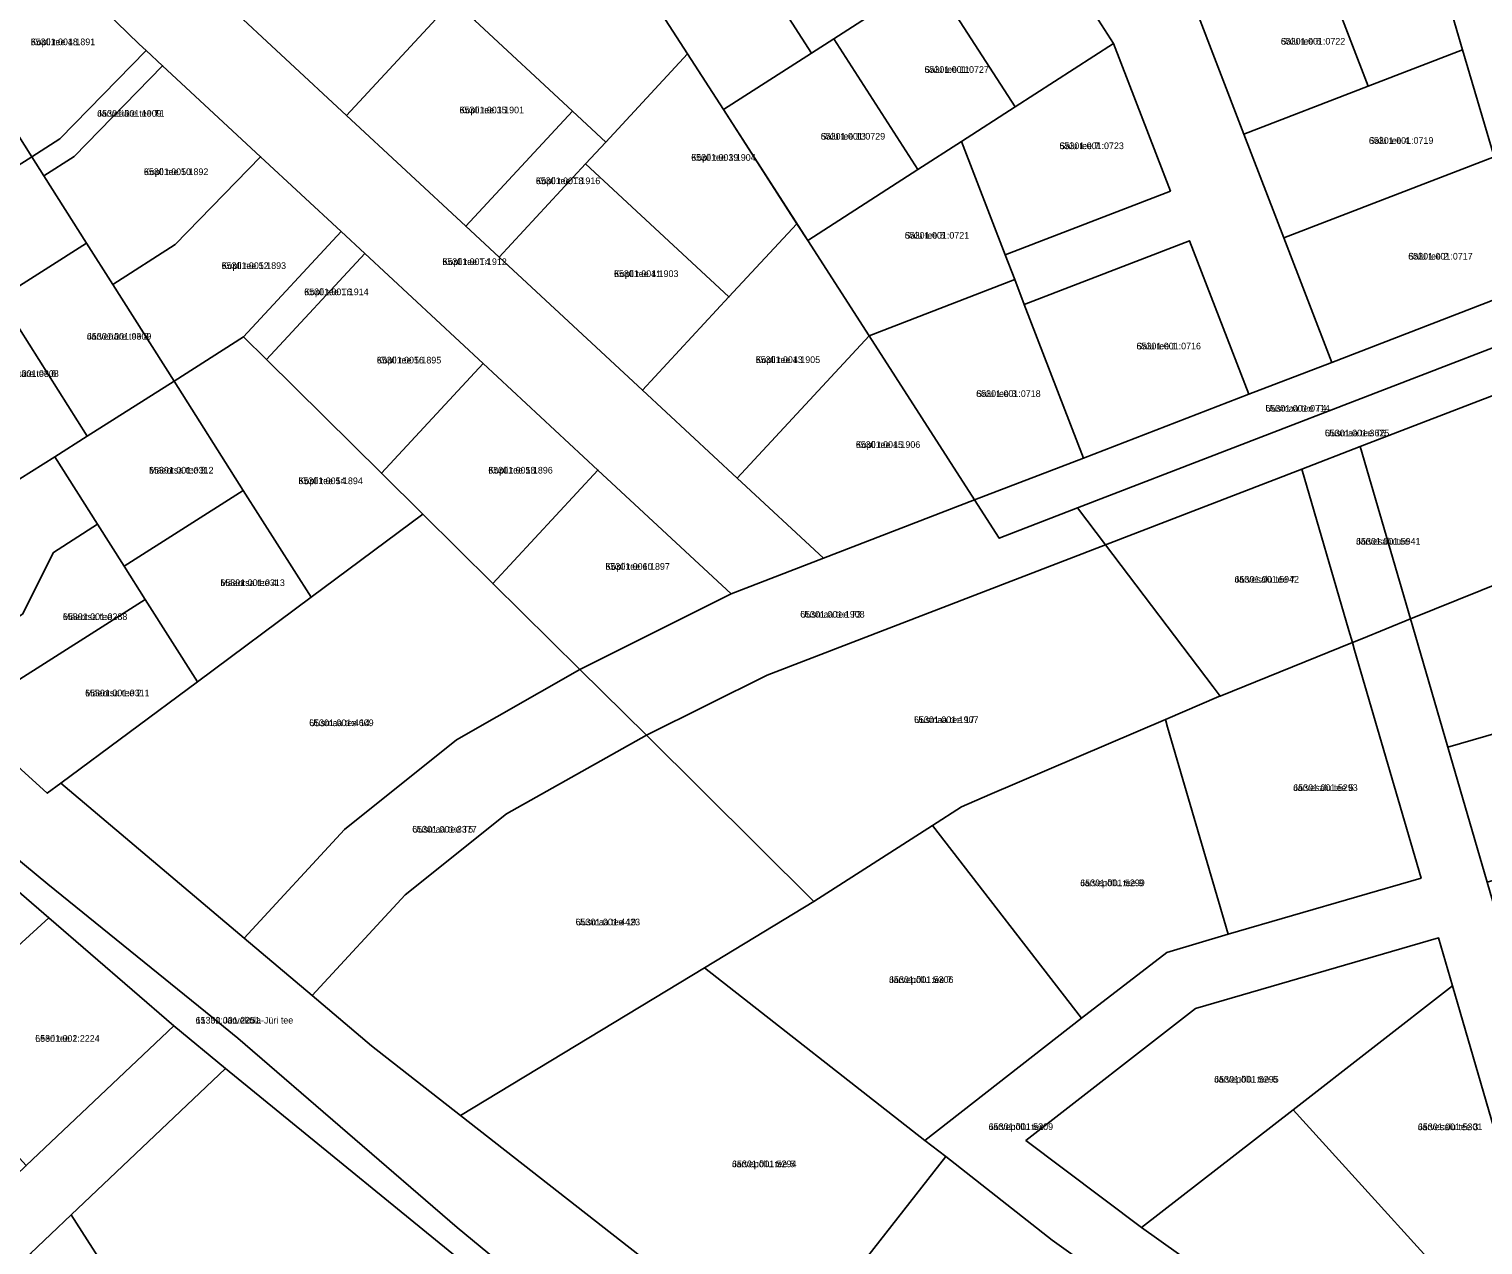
# Model space of a CAD drawing. Extents: x 543236 to 563717, y 6566033 to 6588992.
# Drawn here: x 545303.2 to 545630.4, y 6584014.2 to 6584287.7 of the extents above; entities that cross this region are included whole.
import ezdxf

# ---------------------------------------------------------------- set-up
doc = ezdxf.new("R2010")
doc.units = 0
for name, color, linetype in [('L_AADRESS', 7, 'Continuous'), ('PIIR', 7, 'Continuous'), ('TUNNUS', 7, 'Continuous')]:
    doc.layers.add(name, color=color, linetype=linetype)

msp = doc.modelspace()

# ---------------------------------------------------------------- linework, layer by layer
at = {"layer": 'PIIR'}
for points in [[(545612.18, 6584329.34), (545667.39, 6584358.85), (545675.07, 6584344.48), (545698.18, 6584306.68), (545692.06, 6584302.94), (545696.57, 6584295.46), (545702.81, 6584299.16), (545716.82, 6584276.21), (545641.37, 6584230.07), (545632.88, 6584258.94), (545625.8, 6584283.01), (545615.16, 6584319.21)], [(545591.04, 6584309.91), (545615.16, 6584319.21), (545625.8, 6584283.01), (545604.56, 6584274.83), (545593.2, 6584304.32)], [(545347.2, 6584293.73), (545365.08, 6584312.07), (545374.36, 6584316.68), (545398.67, 6584294.12), (545374.65, 6584268.24)], [(545403.55, 6584289.59), (545428.95, 6584316.96), (545437.53, 6584303.64), (545451.4, 6584282.08), (545432.99, 6584262.25), (545425.51, 6584269.2)], [(545437.53, 6584303.64), (545457.33, 6584316.38), (545472.78, 6584292.38), (545479.27, 6584282.29), (545459.47, 6584269.55)], [(545506.15, 6584299.59), (545528.32, 6584313.86), (545547.27, 6584284.42), (545525.09, 6584270.15)], [(545277.65, 6584300.25), (545305.02, 6584309.24), (545309.36, 6584302.45), (545312.61, 6584299.31), (545328.02, 6584284.27), (545329.53, 6584282.87), (545310.17, 6584263.01), (545303.83, 6584258.96), (545293.5, 6584275.25), (545288.57, 6584283.02), (545283.65, 6584290.79)], [(545312.61, 6584299.31), (545316.44, 6584301.26), (545319.44, 6584302.75), (545331.19, 6584308.57), (545347.2, 6584293.73), (545374.65, 6584268.24), (545401.49, 6584243.33), (545408.98, 6584236.38), (545441.22, 6584206.45), (545462.52, 6584186.68), (545481.97, 6584168.63), (545461.22, 6584160.63), (545431.23, 6584188.46), (545405.41, 6584212.43), (545378.77, 6584237.16), (545373.41, 6584242.13), (545355.3, 6584258.94), (545333.24, 6584279.42), (545329.53, 6584282.87), (545328.02, 6584284.27)], [(545565.2, 6584293.52), (545593.2, 6584304.32), (545604.56, 6584274.83), (545576.56, 6584264.03)], [(545484.28, 6584285.51), (545506.15, 6584299.59), (545525.09, 6584270.15), (545513.03, 6584262.38), (545503.23, 6584256.08)], [(545374.65, 6584268.24), (545398.67, 6584294.12), (545403.55, 6584289.59), (545425.51, 6584269.2), (545401.49, 6584243.33)], [(545459.47, 6584269.55), (545479.27, 6584282.29), (545484.28, 6584285.51), (545503.23, 6584256.08), (545478.42, 6584240.11)], [(545303.83, 6584258.96), (545310.17, 6584263.01), (545329.53, 6584282.87), (545333.24, 6584279.42), (545313.33, 6584258.99), (545306.55, 6584254.66)], [(545513.03, 6584262.38), (545525.09, 6584270.15), (545547.27, 6584284.42), (545560.05, 6584251.25), (545522.84, 6584236.91)], [(545576.56, 6584264.03), (545604.56, 6584274.83), (545625.8, 6584283.01), (545632.88, 6584258.94), (545585.55, 6584240.71)], [(545306.55, 6584254.66), (545313.33, 6584258.99), (545333.24, 6584279.42), (545355.3, 6584258.94), (545336.06, 6584239.22), (545322.04, 6584230.24), (545316.15, 6584239.53)], [(545428.44, 6584257.35), (545432.99, 6584262.25), (545451.4, 6584282.08), (545459.47, 6584269.55), (545475.98, 6584243.89), (545460.68, 6584227.42)], [(545293.5, 6584275.25), (545303.83, 6584258.96), (545275.29, 6584240.86), (545264.95, 6584257.15)], [(545401.49, 6584243.33), (545425.51, 6584269.2), (545432.99, 6584262.25), (545428.44, 6584257.35), (545408.98, 6584236.38)], [(545478.42, 6584240.11), (545503.23, 6584256.08), (545513.03, 6584262.38), (545522.84, 6584236.91), (545525, 6584231.31), (545492.22, 6584218.68)], [(545303.83, 6584258.96), (545306.55, 6584254.66), (545316.15, 6584239.53), (545296.61, 6584227.14), (545292.25, 6584234.03), (545274.49, 6584222.77), (545256.48, 6584211.35), (545230.26, 6584185.73), (545221.37, 6584193.81), (545226.59, 6584198.99), (545222.37, 6584203.25), (545216.92, 6584197.85), (545205.45, 6584208.27), (545215.52, 6584219.38), (545232.18, 6584204.25), (545244.15, 6584216), (545251.22, 6584222.04), (545258.99, 6584226.97), (545271.83, 6584235.11), (545276.89, 6584238.32), (545275.29, 6584240.86)], [(545322.04, 6584230.24), (545336.06, 6584239.22), (545355.3, 6584258.94), (545373.41, 6584242.13), (545351.46, 6584218.48), (545335.83, 6584208.5)], [(545408.98, 6584236.38), (545428.44, 6584257.35), (545460.68, 6584227.42), (545441.22, 6584206.45)], [(545585.55, 6584240.71), (545632.88, 6584258.94), (545641.37, 6584230.07), (545596.34, 6584212.71)], [(545441.22, 6584206.45), (545460.68, 6584227.42), (545475.98, 6584243.89), (545478.42, 6584240.11), (545492.22, 6584218.68), (545462.52, 6584186.68)], [(545351.46, 6584218.48), (545373.41, 6584242.13), (545378.77, 6584237.16), (545356.66, 6584213.33)], [(545527.16, 6584225.71), (545564.37, 6584240.05), (545577.67, 6584205.52), (545540.46, 6584191.18)], [(545316.15, 6584239.53), (545322.04, 6584230.24), (545335.83, 6584208.5), (545316.29, 6584196.11), (545296.61, 6584227.14)], [(545356.66, 6584213.33), (545378.77, 6584237.16), (545405.41, 6584212.43), (545382.51, 6584187.76)], [(545292.25, 6584234.03), (545296.61, 6584227.14), (545316.29, 6584196.11), (545309, 6584191.48), (545298.54, 6584184.85), (545274.49, 6584222.77)], [(545492.22, 6584218.68), (545525, 6584231.31), (545527.16, 6584225.71), (545540.46, 6584191.18), (545515.98, 6584181.75)], [(545515.98, 6584181.75), (545540.46, 6584191.18), (545577.67, 6584205.52), (545596.34, 6584212.71), (545641.37, 6584230.07), (545644.2, 6584220.44), (545539.13, 6584179.98), (545521.51, 6584173.16)], [(545589.61, 6584188.69), (545545.44, 6584171.67), (545539.13, 6584179.98), (545644.2, 6584220.44), (545647.04, 6584210.83), (545602.73, 6584193.75)], [(545335.83, 6584208.5), (545351.46, 6584218.48), (545356.66, 6584213.33), (545382.51, 6584187.76), (545391.8, 6584178.56), (545366.66, 6584159.89), (545351.42, 6584183.91)], [(545462.52, 6584186.68), (545492.22, 6584218.68), (545515.98, 6584181.75), (545481.97, 6584168.63)], [(545382.51, 6584187.76), (545405.41, 6584212.43), (545431.23, 6584188.46), (545407.54, 6584162.96), (545391.8, 6584178.56)], [(545614.04, 6584154.98), (545602.73, 6584193.75), (545647.04, 6584210.83), (545658.68, 6584171.22), (545645.72, 6584167.8)], [(545335.83, 6584208.5), (545351.42, 6584183.91), (545324.59, 6584166.89), (545318.64, 6584176.28), (545309, 6584191.48), (545316.29, 6584196.11)], [(545309, 6584191.48), (545318.64, 6584176.28), (545308.69, 6584169.97), (545301.71, 6584156.08), (545278.87, 6584141.59), (545258.91, 6584159.72), (545280.53, 6584173.43), (545298.54, 6584184.85)], [(545600.19, 6584152.36), (545589.61, 6584188.69), (545602.73, 6584193.75), (545614.04, 6584154.98), (545603.14, 6584150.55), (545600.98, 6584149.67)], [(545407.54, 6584162.96), (545431.23, 6584188.46), (545461.22, 6584160.63), (545427.18, 6584143.62)], [(545569.65, 6584139.73), (545545.44, 6584171.67), (545589.61, 6584188.69), (545600.19, 6584152.36), (545600.98, 6584149.67), (545571.22, 6584137.62)], [(545351.42, 6584183.91), (545366.66, 6584159.89), (545341.1, 6584140.87), (545329.35, 6584159.39), (545324.59, 6584166.89)], [(545427.18, 6584143.62), (545461.22, 6584160.63), (545481.97, 6584168.63), (545515.98, 6584181.75), (545521.51, 6584173.16), (545539.13, 6584179.98), (545545.44, 6584171.67), (545469.29, 6584142.31), (545442.16, 6584128.83)], [(545366.66, 6584159.89), (545391.8, 6584178.56), (545407.54, 6584162.96), (545427.18, 6584143.62), (545399.42, 6584127.78), (545374.18, 6584107.66), (545351.64, 6584083.21), (545310.33, 6584118.05), (545341.1, 6584140.87)], [(545212.59, 6584169.83), (545213.47, 6584170.7), (545217.62, 6584174.69), (545257.23, 6584138.18), (545270.35, 6584126.61), (545286.81, 6584112.39), (545307.45, 6584095.3), (545342.89, 6584066.65), (545350.19, 6584060.71), (545399.54, 6584018.08), (545436.69, 6583987.47), (545474.84, 6583958.99), (545470.74, 6583953.26), (545409.72, 6584003.02), (545347.4, 6584053.85), (545335.77, 6584063.49), (545307.68, 6584087.74), (545277.94, 6584113.41), (545243, 6584143.58)], [(545318.64, 6584176.28), (545324.59, 6584166.89), (545329.35, 6584159.39), (545288.08, 6584133.22), (545278.87, 6584141.59), (545301.71, 6584156.08), (545308.69, 6584169.97)], [(545442.16, 6584128.83), (545469.29, 6584142.31), (545545.44, 6584171.67), (545569.65, 6584139.73), (545571.22, 6584137.62), (545570.95, 6584137.51), (545558.9, 6584132.37), (545519.38, 6584115.5), (545513.01, 6584112.71), (545506.49, 6584108.5), (545479.83, 6584091.47)], [(545614.56, 6584153.2), (545614.04, 6584154.98), (545645.72, 6584167.8), (545658.68, 6584171.22), (545668.08, 6584139.32), (545622.46, 6584126.14)], [(545329.35, 6584159.39), (545341.1, 6584140.87), (545310.33, 6584118.05), (545307.29, 6584115.78), (545288.08, 6584133.22)], [(545559.4, 6584130.62), (545558.9, 6584132.37), (545570.95, 6584137.51), (545571.22, 6584137.62), (545600.98, 6584149.67), (545601.48, 6584147.97), (545616.45, 6584096.72), (545573.02, 6584084.05)], [(545366.92, 6584070.26), (545351.64, 6584083.21), (545374.18, 6584107.66), (545399.42, 6584127.78), (545427.18, 6584143.62), (545442.16, 6584128.83), (545410.67, 6584111.17), (545387.84, 6584092.97)], [(545631.3, 6584095.78), (545622.46, 6584126.14), (545668.08, 6584139.32), (545670.43, 6584131.35), (545676.89, 6584109)], [(545540.06, 6584065.17), (545506.49, 6584108.5), (545513.01, 6584112.71), (545519.38, 6584115.5), (545558.9, 6584132.37), (545559.4, 6584130.62), (545573.02, 6584084.05), (545559.24, 6584080)], [(545387.84, 6584092.97), (545410.67, 6584111.17), (545442.16, 6584128.83), (545479.83, 6584091.47), (545455.17, 6584076.54), (545400.3, 6584043.32), (545380.24, 6584059), (545366.92, 6584070.26)], [(545277.16, 6584059.95), (545250.9, 6584088.79), (545277.94, 6584113.41), (545307.68, 6584087.74)], [(545504.75, 6584037.71), (545455.17, 6584076.54), (545479.83, 6584091.47), (545506.49, 6584108.5), (545540.06, 6584065.17)], [(545277.16, 6584059.95), (545307.68, 6584087.74), (545335.77, 6584063.49), (545302.59, 6584032.02)], [(545553.55, 6584018.14), (545527.54, 6584037.71), (545565.7, 6584067.34), (545620.37, 6584083.26), (545623.49, 6584072.43), (545587.63, 6584044.56)], [(545472.49, 6583986.81), (545400.3, 6584043.32), (545455.17, 6584076.54), (545504.75, 6584037.71), (545509.47, 6584034.05)], [(545633.92, 6583993.55), (545587.63, 6584044.56), (545623.49, 6584072.43), (545643.82, 6584002.66)], [(545184.39, 6583922.14), (545187.41, 6583925.03), (545202.59, 6583938.1), (545222.62, 6583956.17), (545250.92, 6583983.02), (545260.06, 6583991.69), (545293.45, 6584023.35), (545302.59, 6584032.02), (545335.77, 6584063.49), (545347.4, 6584053.85), (545312.69, 6584020.93), (545303.56, 6584012.25), (545263.51, 6583974.28), (545254.34, 6583965.59), (545226.41, 6583939.39), (545217.05, 6583930.95), (545186.41, 6583903.29), (545183.3, 6583905.86), (545191.99, 6583913.79)], [(545312.69, 6584020.93), (545347.4, 6584053.85), (545409.72, 6584003.02), (545381.28, 6583963.21), (545322.94, 6584004.89)], [(545608.94, 6583978.69), (545553.55, 6584018.14), (545587.63, 6584044.56), (545633.92, 6583993.55), (545612.76, 6583974.48)], [(545497.57, 6583967.21), (545472.49, 6583986.81), (545509.47, 6584034.05), (545533.47, 6584015.24), (545572.68, 6583987.32), (545537.86, 6583938.49)], [(545307.09, 6583923.8), (545266.41, 6583952.86), (545254.34, 6583965.59), (545263.51, 6583974.28), (545274.79, 6583962.43), (545275.28, 6583962.08), (545307.39, 6583939.01), (545356.24, 6583904.18), (545380.64, 6583938.37), (545371.66, 6583954.62), (545340.53, 6583976.87), (545336.5, 6583979.74), (545314.08, 6583995.73), (545310.09, 6584002.03), (545303.56, 6584012.25), (545312.69, 6584020.93), (545322.94, 6584004.89), (545381.28, 6583963.21), (545395.56, 6583937.53), (545359.17, 6583886.59)]]:
    msp.add_lwpolyline(points, close=True, dxfattribs=at)
for points in [[(545565.2, 6584293.52), (545576.56, 6584264.03), (545585.55, 6584240.71), (545596.34, 6584212.71), (545577.67, 6584205.52), (545564.37, 6584240.05), (545527.16, 6584225.71), (545525, 6584231.31), (545522.84, 6584236.91), (545560.05, 6584251.25), (545547.27, 6584284.42), (545528.32, 6584313.86)], [(545506.15, 6584299.59), (545484.28, 6584285.51), (545479.27, 6584282.29), (545472.78, 6584292.38)], [(545436.69, 6583987.47), (545399.54, 6584018.08), (545350.19, 6584060.71), (545342.89, 6584066.65), (545307.45, 6584095.3), (545286.81, 6584112.39), (545270.35, 6584126.61), (545257.23, 6584138.18), (545217.62, 6584174.69), (545213.47, 6584170.7), (545212.86, 6584179.01), (545226.88, 6584188.8), (545258.91, 6584159.72), (545278.87, 6584141.59), (545288.08, 6584133.22), (545307.29, 6584115.78), (545310.33, 6584118.05), (545351.64, 6584083.21), (545366.92, 6584070.26), (545380.24, 6584059), (545400.3, 6584043.32), (545472.49, 6583986.81)], [(545572.68, 6583987.32), (545533.47, 6584015.24), (545509.47, 6584034.05), (545504.75, 6584037.71), (545540.06, 6584065.17), (545559.24, 6584080), (545573.02, 6584084.05), (545616.45, 6584096.72), (545601.48, 6584147.97), (545600.98, 6584149.67), (545603.14, 6584150.55), (545614.04, 6584154.98), (545614.56, 6584153.2), (545622.46, 6584126.14), (545631.3, 6584095.78), (545640.15, 6584065.44), (545648.99, 6584035.06), (545657.84, 6584004.67)], [(545643.82, 6584002.66), (545623.49, 6584072.43), (545620.37, 6584083.26), (545565.7, 6584067.34), (545527.54, 6584037.71), (545553.55, 6584018.14), (545608.94, 6583978.69)]]:
    msp.add_lwpolyline(points, dxfattribs=at)

# ---------------------------------------------------------------- texts
at = {"layer": 'L_AADRESS'}
for s, p in [('Kopli tee 48', (545303.59, 6584284.05)), ('Salu tee 6', (545584.88, 6584284.18)), ('Salu tee 11', (545504.69, 6584277.83)), ('Järveääre tee T1', (545318.54, 6584267.96)), ('Kopli tee 35', (545400.08, 6584268.73)), ('Salu tee 13', (545481.35, 6584262.81)), ('Salu tee 4', (545604.71, 6584261.86)), ('Kopli tee 39', (545452.21, 6584258.05)), ('Salu tee 7', (545535.06, 6584260.67)), ('Kopli tee 50', (545329.05, 6584254.83)), ('Kopli tee T8', (545417.24, 6584252.79)), ('Salu tee 5', (545500.26, 6584240.53)), ('Salu tee 2', (545613.56, 6584235.83)), ('Kopli tee 52', (545346.54, 6584233.72)), ('Kopli tee T4', (545396.21, 6584234.6)), ('Kopli tee 41', (545434.83, 6584231.9)), ('Kopli tee T6', (545365.12, 6584227.82)), ('Järveääre tee 8', (545316.22, 6584217.82)), ('Salu tee 1', (545552.41, 6584215.62)), ('Kopli tee 56', (545381.46, 6584212.46)), ('Kopli tee 43', (545466.72, 6584212.56)), ('Järveääre tee 6', (545295.39, 6584209.44)), ('Salu tee 3', (545516.34, 6584204.93)), ('Uusmaa tee T4', (545581.43, 6584201.62)), ('Uusmaa tee T6', (545594.79, 6584196.06)), ('Kopli tee 45', (545489.25, 6584193.46)), ('Mäeotsa tee 3', (545330.21, 6584187.7)), ('Kopli tee 58', (545406.55, 6584187.7)), ('Kopli tee 54', (545363.81, 6584185.31)), ('Järvesalu tee', (545601.82, 6584171.71)), ('Kopli tee 60', (545432.9, 6584166.04)), ('Järvesalu tee 7', (545574.47, 6584163.16)), ('Mäeotsa tee 4', (545346.26, 6584162.39)), ('Mäeotsa tee', (545310.82, 6584154.75)), ('Uusmaa tee T3', (545476.74, 6584155.29)), ('Mäeotsa tee 2', (545315.82, 6584137.59)), ('Uusmaa tee 14', (545366.25, 6584130.88)), ('Uusmaa tee 17', (545502.35, 6584131.57)), ('Järvesalu tee 5', (545587.68, 6584116.3)), ('Uusmaa tee T5', (545389.44, 6584106.94)), ('Järvepõllu tee 9', (545539.76, 6584094.88)), ('Uusmaa tee 19', (545426.2, 6584086.07)), ('Järvepõllu tee 7', (545496.73, 6584073.11)), ('11330 Järveküla-Jüri tee', (545340.69, 6584063.98)), ('Leeri tee 2', (545304.59, 6584059.88)), ('Järvepõllu tee 6', (545569.9, 6584050.7)), ('Järvepõllu tee', (545519.14, 6584040.04)), ('Järvesalu tee 3', (545615.73, 6584040)), ('Järvepõllu tee 5', (545461.39, 6584031.67))]:
    msp.add_text(s, height=1.5, dxfattribs=at).set_placement(p)
at = {"layer": 'TUNNUS'}
for s, p in [('65301:001:1891', (545303.59, 6584284.05)), ('65301:001:0722', (545584.88, 6584284.18)), ('65301:001:0727', (545504.69, 6584277.83)), ('65301:001:1909', (545318.54, 6584267.96)), ('65301:001:1901', (545400.08, 6584268.73)), ('65301:001:0729', (545481.35, 6584262.81)), ('65301:001:0719', (545604.71, 6584261.86)), ('65301:001:1904', (545452.21, 6584258.05)), ('65301:001:0723', (545535.06, 6584260.67)), ('65301:001:1892', (545329.05, 6584254.83)), ('65301:001:1916', (545417.24, 6584252.79)), ('65301:001:0721', (545500.26, 6584240.53)), ('65301:001:0717', (545613.56, 6584235.83)), ('65301:001:1893', (545346.54, 6584233.72)), ('65301:001:1912', (545396.21, 6584234.6)), ('65301:001:1903', (545434.83, 6584231.9)), ('65301:001:1914', (545365.12, 6584227.82)), ('65301:001:0309', (545316.22, 6584217.82)), ('65301:001:0716', (545552.41, 6584215.62)), ('65301:001:1895', (545381.46, 6584212.46)), ('65301:001:1905', (545466.72, 6584212.56)), ('65301:001:0308', (545295.39, 6584209.44)), ('65301:001:0718', (545516.34, 6584204.93)), ('65301:001:0714', (545581.43, 6584201.62)), ('65301:001:3625', (545594.79, 6584196.06)), ('65301:001:1906', (545489.25, 6584193.46)), ('65301:001:0312', (545330.21, 6584187.7)), ('65301:001:1896', (545406.55, 6584187.7)), ('65301:001:1894', (545363.81, 6584185.31)), ('65301:001:5941', (545601.82, 6584171.71)), ('65301:001:1897', (545432.9, 6584166.04)), ('65301:001:5942', (545574.47, 6584163.16)), ('65301:001:0313', (545346.26, 6584162.39)), ('65301:001:0288', (545310.82, 6584154.75)), ('65301:001:1908', (545476.74, 6584155.29)), ('65301:001:0311', (545315.82, 6584137.59)), ('65301:001:4609', (545366.25, 6584130.88)), ('65301:001:1907', (545502.35, 6584131.57)), ('65301:001:5293', (545587.68, 6584116.3)), ('65301:001:3377', (545389.44, 6584106.94)), ('65301:001:5299', (545539.76, 6584094.88)), ('65301:001:4423', (545426.2, 6584086.07)), ('65301:001:5306', (545496.73, 6584073.11)), ('65301:001:2251', (545340.69, 6584063.98)), ('65301:001:2224', (545304.59, 6584059.88)), ('65301:001:5295', (545569.9, 6584050.7)), ('65301:001:5309', (545519.14, 6584040.04)), ('65301:001:5301', (545615.73, 6584040)), ('65301:001:5294', (545461.39, 6584031.67))]:
    msp.add_text(s, height=1.5, dxfattribs=at).set_placement(p)

doc.saveas('drawing.dxf')
